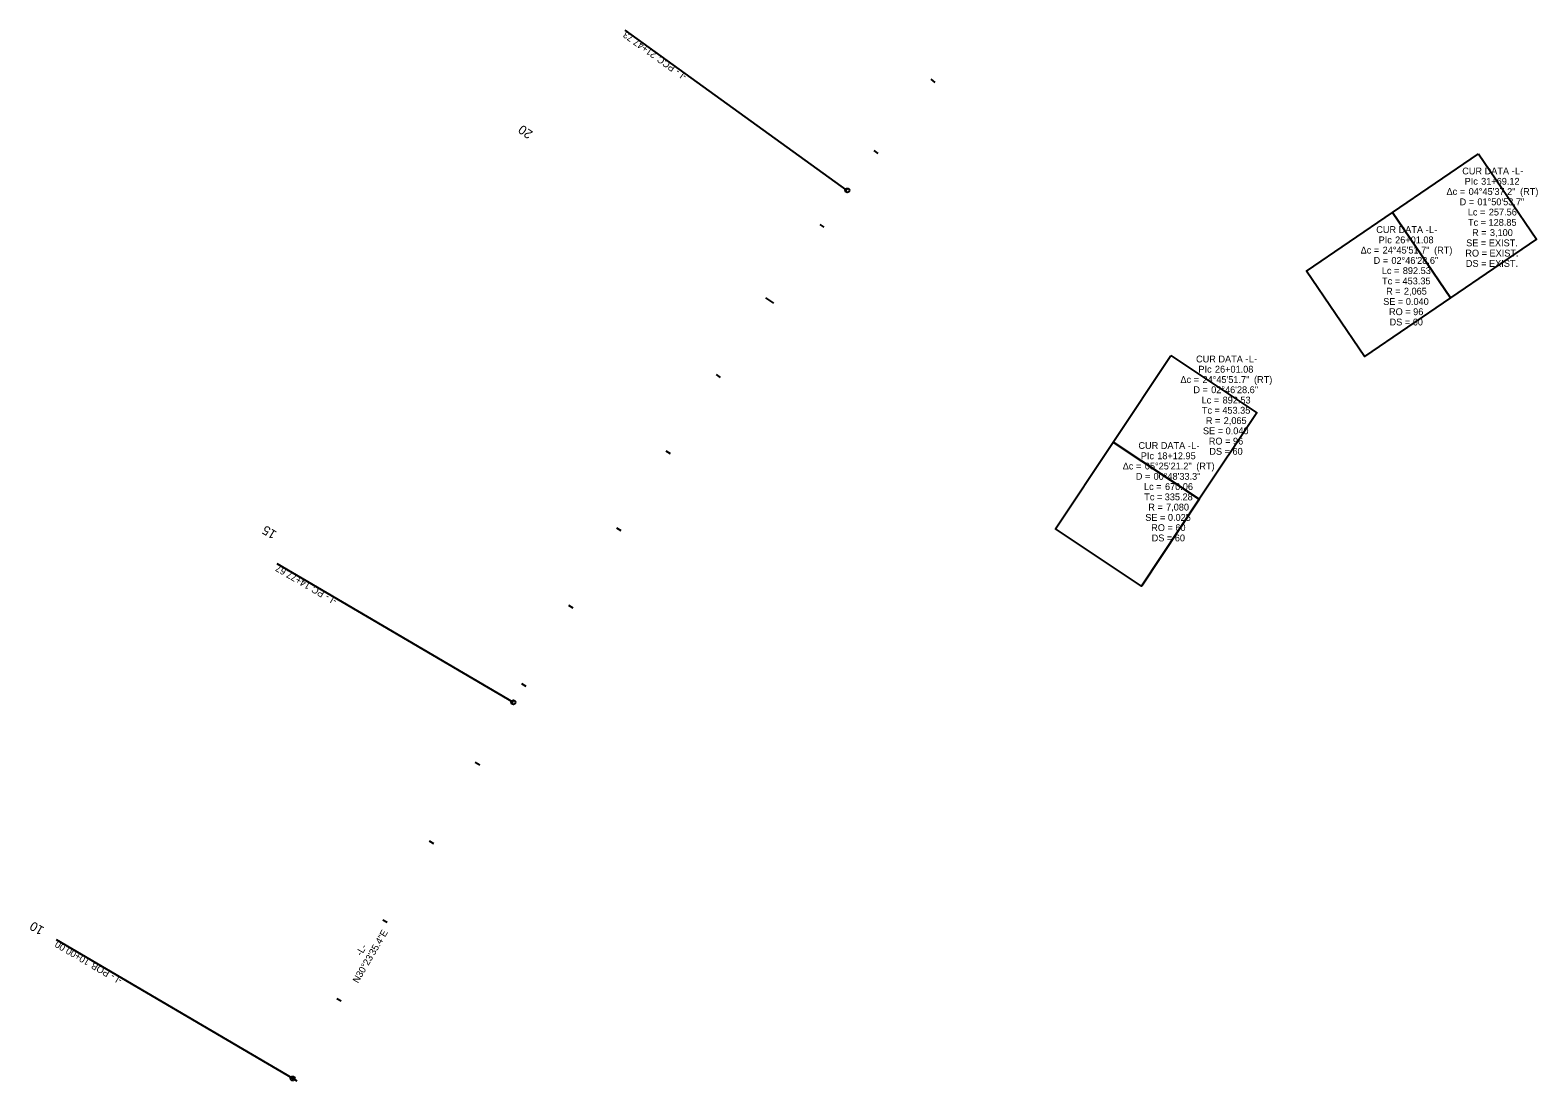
# Model space of a CAD drawing. Extents: x 2379555 to 2381342, y 331421 to 333377.
# Drawn here: x 2379555 to 2381207, y 331421 to 332572 of the extents above; entities that cross this region are included whole.
import ezdxf

# ---------------------------------------------------------------- set-up
doc = ezdxf.new("R2010")
doc.units = 0
for name, color, linetype in [('_CIVIL_CONSTRUCTION', 7, 'Continuous'), ('P_NCDOT_Horizontal_Alignment_Curve_and_Spiral_Data', 7, 'Continuous'), ('P_NCDOT_Horizontal_Alignment_Direction_Label', 7, 'Continuous'), ('P_NCDOT_Horizontal_Alignment_Station_Label', 7, 'Continuous'), ('P_NCDOT_Horizontal_Alignment_Station_Major_Label', 7, 'Continuous'), ('P_NCDOT_Horizontal_Alignment_Tick_Large', 7, 'Continuous'), ('P_NCDOT_Horizontal_Alignment_Tick_Small', 7, 'Continuous')]:
    doc.layers.add(name, color=color, linetype=linetype)

msp = doc.modelspace()

# ---------------------------------------------------------------- linework, layer by layer
at = {"layer": '_CIVIL_CONSTRUCTION'}
msp.add_circle((2379842.6, 331423.8), 0.05, dxfattribs=at)
at = {"layer": 'P_NCDOT_Horizontal_Alignment_Curve_and_Spiral_Data'}
for points in [[(2381141.4, 332436.9), (2381205.1, 332343.4), (2381111, 332279.2), (2381047.2, 332372.6)], [(2381047.2, 332372.6), (2381111, 332279.2), (2381016.8, 332215), (2380953, 332308.4)], [(2380804.5, 332215.9), (2380898.6, 332153.3), (2380835.5, 332058.4), (2380741.3, 332121)], [(2380741.3, 332121), (2380835.5, 332058.4), (2380772.3, 331963.4), (2380678.1, 332026.1)]]:
    msp.add_lwpolyline(points, close=True, dxfattribs=at)
at = {"layer": 'P_NCDOT_Horizontal_Alignment_Station_Label'}
for p, q in [((2380450.1, 332396.9), (2380206.8, 332572.5)), ((2380084.3, 331835.9), (2379825.5, 331987.6)), ((2379842.6, 331423.8), (2379583.8, 331575.6))]:
    msp.add_line(p, q, dxfattribs=at)
for centre in [(2380450.1, 332396.9), (2380084.3, 331835.9), (2379842.6, 331423.8)]:
    msp.add_circle(centre, 2.25, dxfattribs=at)
at = {"layer": 'P_NCDOT_Horizontal_Alignment_Tick_Large'}
for p, q in [((2380360.5, 332279.3), (2380369.3, 332273.2)), ((2379838, 331426.5), (2379847.2, 331421.2))]:
    msp.add_line(p, q, dxfattribs=at)
at = {"layer": 'P_NCDOT_Horizontal_Alignment_Tick_Small'}
for p, q in [((2380541.6, 332518.8), (2380545.8, 332515.2)), ((2380479, 332440.6), (2380483.4, 332437.3)), ((2380420.1, 332359.7), (2380424.5, 332356.5)), ((2380306.4, 332195.1), (2380311, 332192)), ((2380251.3, 332111.6), (2380255.9, 332108.6)), ((2380197.4, 332027.3), (2380202.1, 332024.4)), ((2380144.7, 331942.3), (2380149.4, 331939.4)), ((2380093.2, 331856.5), (2380098, 331853.7)), ((2380042.6, 331770.3), (2380047.4, 331767.5)), ((2379992, 331684), (2379996.8, 331681.2)), ((2379941.4, 331597.7), (2379946.2, 331594.9)), ((2379890.8, 331511.5), (2379895.6, 331508.7))]:
    msp.add_line(p, q, dxfattribs=at)

# ---------------------------------------------------------------- texts
at = {"layer": 'P_NCDOT_Horizontal_Alignment_Curve_and_Spiral_Data'}
for s, p in [('CUR DATA -', (2381123.7, 332414.4)), ('L', (2381181.5, 332414.4)), ('PIc ', (2381126.3, 332403.1)), ('31+69.12', (2381144.4, 332403.1)), ('-', (2381187.3, 332414.4)), ('Δc = ', (2381106.5, 332391.9)), ('D = ', (2381120.8, 332380.6)), ('04°45\'37.2"', (2381130.7, 332391.9)), ('01°50\'53.7"', (2381140.3, 332380.6)), (' (RT)', (2381184.3, 332391.9)), ('Lc = ', (2381129.8, 332369.4)), ('257.56', (2381152.8, 332369.4)), ('CUR DATA -', (2381029.5, 332350.2)), ('L', (2381087.3, 332350.2)), ('Tc = ', (2381130, 332358.1)), ('R = ', (2381134.5, 332346.9)), ('128.85', (2381152.5, 332358.1)), ('3,100', (2381154, 332346.9)), ('PIc ', (2381032.1, 332338.9)), ('26+01.08', (2381050.2, 332338.9)), ('-', (2381093.2, 332350.2)), ('SE = EXIST.', (2381128, 332335.6)), ('Δc = ', (2381012.4, 332327.7)), ('D = ', (2381026.6, 332316.4)), ('24°45\'51.7"', (2381036.5, 332327.7)), ('02°46\'28.6"', (2381046.1, 332316.4)), (' (RT)', (2381090.1, 332327.7)), ('RO = EXIST.', (2381127.1, 332324.4)), ('Lc = ', (2381035.6, 332305.2)), ('892.53', (2381058.6, 332305.2)), ('DS = EXIST.', (2381127.7, 332313.1)), ('Tc = ', (2381035.9, 332293.9)), ('R = ', (2381040.3, 332282.7)), ('453.35', (2381058.3, 332293.9)), ('2,065', (2381059.8, 332282.7)), ('SE = 0.040', (2381037.1, 332271.4)), ('RO = 96', (2381043.5, 332260.2)), ('DS = 60', (2381044.1, 332248.9)), ('CUR DATA -', (2380832.1, 332208.4)), ('L', (2380889.9, 332208.4)), ('-', (2380895.8, 332208.4)), ('Δc = ', (2380815, 332185.9)), ('PIc ', (2380834.7, 332197.2)), ('24°45\'51.7"', (2380839.2, 332185.9)), ('26+01.08', (2380852.8, 332197.2)), (' (RT)', (2380892.8, 332185.9)), ('D = ', (2380829.2, 332174.7)), ('02°46\'28.6"', (2380848.7, 332174.7)), ('Tc = ', (2380838.5, 332152.2)), ('Lc = ', (2380838.2, 332163.4)), ('453.35', (2380860.9, 332152.2)), ('892.53', (2380861.2, 332163.4)), ('R = ', (2380842.9, 332140.9)), ('2,065', (2380862.4, 332140.9)), ('SE = 0.040', (2380839.7, 332129.7)), ('RO = 96', (2380846.1, 332118.4)), ('CUR DATA -', (2380769, 332113.6)), ('PIc ', (2380771.6, 332102.3)), ('18+12.95', (2380789.6, 332102.3)), ('L', (2380826.8, 332113.6)), ('-', (2380832.6, 332113.6)), ('DS = 60', (2380846.7, 332107.2)), ('Δc = ', (2380751.8, 332091.1)), ('05°25\'21.2"', (2380776, 332091.1)), (' (RT)', (2380829.6, 332091.1)), ('D = ', (2380766.1, 332079.8)), ('Lc = ', (2380775.1, 332068.6)), ('00°48\'33.3"', (2380785.6, 332079.8)), ('670.06', (2380798.1, 332068.6)), ('Tc = ', (2380775.4, 332057.3)), ('335.28', (2380797.8, 332057.3)), ('SE = 0.025', (2380776.5, 332034.8)), ('R = ', (2380779.8, 332046.1)), ('7,080', (2380799.3, 332046.1)), ('RO = 60', (2380783, 332023.6)), ('DS = 60', (2380783.5, 332012.3))]:
    msp.add_text(s, height=7.5, dxfattribs=at).set_placement(p)
at = {"layer": 'P_NCDOT_Horizontal_Alignment_Direction_Label'}
for s, p in [('N30°23\'35.4"E', (2379914.1, 331527.6)), ('L', (2379919.5, 331560.4)), ('-', (2379917.7, 331557.4)), ('-', (2379922.4, 331565.4))]:
    msp.add_text(s, height=7.5, rotation=59.6068, dxfattribs=at).set_placement(p)
at = {"layer": 'P_NCDOT_Horizontal_Alignment_Station_Label'}
for s, rotation, p in [('21+47.73', 144.1843, (2380242.1, 332547)), ('PCC', 144.1843, (2380262.4, 332532.4)), ('- ', 144.1843, (2380267.6, 332528.6)), ('L', 144.1843, (2380272.3, 332525.2)), ('-', 144.1843, (2380275.1, 332523.2)), ('14+77.67', 149.6068, (2379863, 331965.6)), ('PC', 149.6068, (2379878.1, 331956.8)), ('- ', 149.6068, (2379883.6, 331953.5)), ('L', 149.6068, (2379888.6, 331950.6)), ('-', 149.6068, (2379891.6, 331948.8)), ('10+00.00', 149.6068, (2379621.3, 331553.6)), ('POB', 149.6068, (2379642.9, 331540.9)), ('- ', 149.6068, (2379648.5, 331537.7)), ('L', 149.6068, (2379653.5, 331534.8)), ('-', 149.6068, (2379656.5, 331533))]:
    msp.add_text(s, height=7.5, rotation=rotation, dxfattribs=at).set_placement(p)
at = {"layer": 'P_NCDOT_Horizontal_Alignment_Station_Major_Label'}
for s, rotation, p in [('20', 145.3798, (2380106.4, 332460.8)), ('15', 149.0736, (2379825.8, 332022.6)), ('10', 149.6068, (2379571.2, 331588.8))]:
    msp.add_text(s, height=10, rotation=rotation, dxfattribs=at).set_placement(p)

doc.saveas('drawing.dxf')
